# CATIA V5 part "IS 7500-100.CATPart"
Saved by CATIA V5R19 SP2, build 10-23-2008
Part number: IS 7500-100
Bounding box of the stored display mesh (mm): x -74.81 to 74.81, y -74.81 to 74.81, z 0 to 355
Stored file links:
  C:\Users\Bora\Desktop\3D Katı model\IS serisi\IS 7500\IS 7500-100.CATPart
  C:\Program Files\Dassault Systemes\B19\intel_a\reffiles\standard\MetricThickPitch.txt
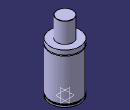
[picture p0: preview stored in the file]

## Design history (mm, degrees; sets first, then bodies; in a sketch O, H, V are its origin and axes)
Body1 (main body)
  Sketch1 on yz-plane, origin (0, 0, 0), H (0, 1, 0), V (0, 0, 1)
    point P1 (75, 230)
    point P4 (75, 225)
    point P7 (40, 354)
    point P9 (40, 354)
    point P13 (75, 230)
    point P14 (75, 225)
    line L1 (75, 230) -> (75, 252)
    line L2 (75, 15) -> (75, 225)
    line L3 (71, 15) -> (71, 8)
    arc A1 centre (39, 354) radius 1 from (40, 354) to (39, 355) ccw
    line L4 (40, 354) -> (40, 252)
    line L5 (75, 0) -> (75, 8)
    arc A2 centre (75, 227.5) radius 2.5 from (75, 230) to (75, 225) ccw
    line L6 (39, 355) -> (0, 355)
    point P15 (0, 355)
    line L7 (40, 252) -> (75, 252)
    line L8 (0, 0) -> (75, 0)
    line L9 (71, 15) -> (75, 15)
    line L10 (71, 8) -> (75, 8)
    coincidence: P15 V, P1 P13, P4 P14, P7 P9
    tangency: L6 A1
    horizontal: L7 H, L8 H, L9 H, L10 H
  Shaft1: profile Sketch1, axis Sketch1.V, angle 360
  Sketch2 on face of Shaft1 from Sketch1.L8, origin (0, 0, 0), H (1, 0, 0), V (0, -1, 0)
    point P1 (50, 0)
    distance P1 V = 50
  Hole1: placed by Sketch2, at (50, 0, 0) direction (0, 0, 1), diameter 8.376, depth 16, threaded "M10", thread diameter 10, thread depth 16, pitch 1.5
  CircPattern1: of Hole1, instances 4, angular step 90, axis from xy-plane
